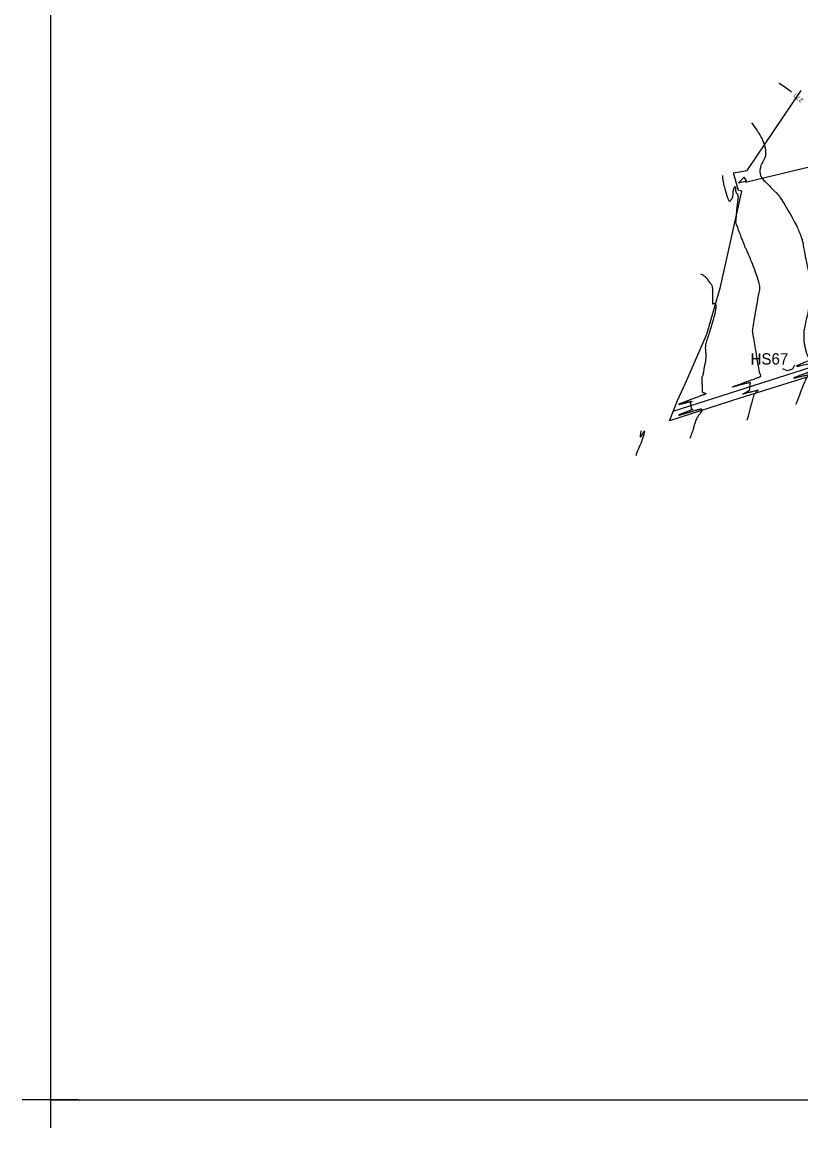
# Model space of a CAD drawing. Extents: x -478645 to -472650, y -1118147 to -1113892.
# Drawn here: x -478645 to -477955, y -1118147 to -1117166 of the extents above; entities that cross this region are included whole.
import ezdxf

# ---------------------------------------------------------------- set-up
doc = ezdxf.new("R2010")
doc.units = 0
for name, color, linetype in [('cestní_příkop_návrh', 7, 'Continuous'), ('cesty', 7, 'Continuous'), ('hospodářské sjezdy', 7, 'Continuous'), ('Implicitní', 7, 'Continuous'), ('ObPÚ', 7, 'Continuous'), ('silnice', 7, 'Continuous'), ('Vrstevnice_hlavni', 7, 'Continuous'), ('Vrstevnice_popis', 7, 'Continuous'), ('Vrstevnice_vedlejsi', 7, 'Continuous'), ('Z_razitko', 7, 'Continuous')]:
    doc.layers.add(name, color=color, linetype=linetype)

msp = doc.modelspace()

# ---------------------------------------------------------------- linework, layer by layer
at = {"layer": 'cestní_příkop_návrh'}
msp.add_lwpolyline([(-478004.329, -1117308.16), (-477706.253, -1117236.161), (-477707.935, -1117239.207)], dxfattribs=at)
at = {"layer": 'cesty'}
msp.add_line((-478003.676, -1117307.068), (-478005.553, -1117303.536), dxfattribs=at)
msp.add_lwpolyline([(-478005.553, -1117303.536), (-478010.749, -1117308.562), (-478003.676, -1117307.068)], dxfattribs=at)
at = {"layer": 'hospodářské sjezdy'}
for p, q in [((-477960.951, -1117470.316), (-477962.923, -1117474.099)), ((-477967.582, -1117475.568), (-477971.367, -1117473.601)), ((-477962.923, -1117474.099), (-477967.582, -1117475.568))]:
    msp.add_line(p, q, dxfattribs=at)
at = {"layer": 'Implicitní'}
for p, q in [((-478620.405, -1118096.842), (-478620.405, -1118146.842)), ((-478620.405, -1118096.842), (-478620.405, -1118146.842)), ((-478620.405, -1118096.842), (-478620.405, -1118146.842)), ((-478620.405, -1118096.842), (-478620.405, -1118146.842)), ((-478595.405, -1118121.842), (-478645.405, -1118121.842)), ((-478595.405, -1118121.842), (-478645.405, -1118121.842)), ((-478595.405, -1118121.842), (-478645.405, -1118121.842)), ((-478595.405, -1118121.842), (-478645.405, -1118121.842))]:
    msp.add_line(p, q, dxfattribs=at)
at = {"layer": 'ObPÚ'}
msp.add_lwpolyline([(-477945.12, -1117479.46), (-478009.37, -1117499.81), (-478071.71, -1117519.91), (-478064.79, -1117501.64), (-478057.71, -1117486.26), (-478038.68, -1117442.8), (-478036.665, -1117435.774), (-478026.64, -1117400.81), (-478007.71, -1117316.06), (-478010.717, -1117315.486), (-478014.94, -1117299.9), (-478003.02, -1117297.83), (-477955.02, -1117226.727)], dxfattribs=at)
at = {"layer": 'silnice'}
msp.add_lwpolyline([(-478068.596, -1117511.329), (-477917.95, -1117462.993), (-477779.219, -1117418.245), (-477732.944, -1117407.585), (-477720.808, -1117405.048), (-477704.588, -1117403.835), (-477689.402, -1117401.926), (-477652.852, -1117401.691), (-477590.784, -1117403.37), (-477332.447, -1117414.279), (-477204.956, -1117416.797), (-477142.049, -1117416.797), (-477096.756, -1117410.083), (-477036.34, -1117397.174), (-476978.492, -1117379.033), (-476883.712, -1117344.626), (-476756.221, -1117298.47), (-476633.763, -1117254.832), (-476588.47, -1117242.245), (-476550.726, -1117234.692)], dxfattribs=at)
at = {"layer": 'Vrstevnice_hlavni'}
msp.add_spline([(-477974.913, -1117220.071), (-477973.154, -1117221.178), (-477963.793, -1117227.865)], degree=3, dxfattribs=at)
at = {"layer": 'Vrstevnice_vedlejsi'}
msp.add_line((-478053.213, -1117534.03), (-478053.687, -1117535.309), dxfattribs=at)
for points in [[(-477998.879, -1117255.557), (-477998.727, -1117255.77), (-477994.613, -1117261.766), (-477989.226, -1117270.883), (-477986.788, -1117279.171), (-477987.299, -1117286.631), (-477990.759, -1117293.261), (-477991.682, -1117299.15), (-477990.068, -1117304.296), (-477985.915, -1117308.701), (-477982.328, -1117312.403), (-477979.306, -1117315.404), (-477976.849, -1117317.702), (-477973.612, -1117321.957), (-477969.594, -1117328.168), (-477964.797, -1117336.336), (-477960.899, -1117343.504), (-477957.9, -1117349.67), (-477955.8, -1117354.835), (-477954.323, -1117359.055), (-477953.469, -1117362.331), (-477953.239, -1117364.661), (-477952.282, -1117369.883), (-477950.598, -1117377.995), (-477948.188, -1117388.997), (-477946.693, -1117397.801), (-477946.113, -1117404.405), (-477946.449, -1117408.81), (-477947.352, -1117414.723), (-477948.823, -1117422.144), (-477950.861, -1117431.072), (-477952.177, -1117437.645), (-477952.771, -1117441.863), (-477952.644, -1117443.726), (-477952.589, -1117445.223), (-477952.606, -1117446.354), (-477952.696, -1117447.119), (-477952.711, -1117448.007), (-477952.649, -1117449.018), (-477952.512, -1117450.153), (-477952.156, -1117452.114), (-477951.583, -1117454.901), (-477950.791, -1117458.515), (-477949.91, -1117461.246), (-477948.939, -1117463.094), (-477947.878, -1117464.059), (-477947.136, -1117464.728), (-477946.712, -1117465.101), (-477946.606, -1117465.179), (-477946.495, -1117465.26), (-477946.379, -1117465.346), (-477946.257, -1117465.436), (-477946.233, -1117465.524), (-477946.307, -1117465.609), (-477946.478, -1117465.691), (-477946.651, -1117465.772), (-477946.824, -1117465.851), (-477946.999, -1117465.928), (-477947.792, -1117466.25), (-477949.203, -1117466.816), (-477951.232, -1117467.627), (-477953.439, -1117468.556), (-477955.824, -1117469.604), (-477958.387, -1117470.771), (-477959.194, -1117471.349), (-477958.243, -1117471.339)], [(-477991.867, -1117477.245), (-477991.928, -1117477.172), (-477992.04, -1117476.677), (-477992.202, -1117475.763), (-477992.413, -1117474.428), (-477993.107, -1117470.277), (-477994.282, -1117463.311), (-477995.94, -1117453.528), (-477997.123, -1117446.591), (-477997.83, -1117442.497), (-477998.062, -1117441.249), (-477997.593, -1117436.785), (-477996.423, -1117429.106), (-477994.553, -1117418.212), (-477993.126, -1117410.136), (-477992.143, -1117404.879), (-477991.604, -1117402.439), (-477992.237, -1117398.118), (-477994.043, -1117391.915), (-477997.021, -1117383.831), (-477999.558, -1117377.283), (-478001.654, -1117372.273), (-478003.307, -1117368.799), (-478004.636, -1117365.887), (-478005.64, -1117363.535), (-478006.319, -1117361.745), (-478007.439, -1117358.786), (-478009, -1117354.657), (-478011.003, -1117349.359), (-478012.316, -1117345.574), (-478012.939, -1117343.304), (-478012.872, -1117342.547), (-478012.777, -1117341.561), (-478012.655, -1117340.344), (-478012.505, -1117338.897), (-478012.348, -1117337.07), (-478012.182, -1117334.863), (-478012.009, -1117332.276), (-478011.775, -1117329.718), (-478011.478, -1117327.189), (-478011.12, -1117324.688), (-478010.876, -1117322.931), (-478010.745, -1117321.917), (-478010.728, -1117321.646), (-478010.753, -1117321.243), (-478010.821, -1117320.708), (-478010.93, -1117320.041), (-478011.029, -1117319.606), (-478011.115, -1117319.402), (-478011.19, -1117319.431), (-478011.241, -1117319.41), (-478011.268, -1117319.341), (-478011.271, -1117319.224), (-478011.447, -1117318.941), (-478011.795, -1117318.493), (-478012.316, -1117317.879), (-478012.672, -1117317.097), (-478012.863, -1117316.147), (-478012.89, -1117315.028), (-478012.892, -1117314.215), (-478012.869, -1117313.71), (-478012.821, -1117313.512), (-478012.909, -1117313.243), (-478013.131, -1117312.902), (-478013.489, -1117312.491), (-478013.809, -1117312.342), (-478014.093, -1117312.455), (-478014.34, -1117312.83), (-478014.581, -1117313.247), (-478014.817, -1117313.705), (-478015.046, -1117314.206), (-478015.238, -1117314.822), (-478015.392, -1117315.554), (-478015.508, -1117316.401), (-478015.602, -1117317.301), (-478015.672, -1117318.253), (-478015.72, -1117319.257), (-478015.808, -1117320.173), (-478015.935, -1117321.003), (-478016.103, -1117321.746), (-478016.33, -1117322.362), (-478016.618, -1117322.853), (-478016.967, -1117323.218), (-478017.343, -1117323.742), (-478017.748, -1117324.426), (-478018.182, -1117325.269), (-478018.755, -1117325.029), (-478019.468, -1117323.706), (-478020.32, -1117321.3), (-478021.282, -1117318.195), (-478022.355, -1117314.389), (-478023.538, -1117309.884), (-478024.297, -1117305.737), (-478024.625, -1117302.334)], [(-478044.323, -1117389.497), (-478042.996, -1117389.964), (-478040.645, -1117391.528), (-478038.938, -1117393.157), (-478037.876, -1117394.852), (-478036.855, -1117396.325), (-478035.874, -1117397.575), (-478034.935, -1117398.602), (-478034.275, -1117399.76), (-478033.895, -1117401.05), (-478033.795, -1117402.47), (-478033.734, -1117403.559), (-478033.712, -1117404.316), (-478033.729, -1117404.741), (-478033.725, -1117405.596), (-478033.699, -1117406.882), (-478033.652, -1117408.598), (-478033.647, -1117410.423), (-478033.685, -1117412.357), (-478033.765, -1117414.398), (-478033.662, -1117415.636), (-478033.377, -1117416.07), (-478032.909, -1117415.7), (-478032.433, -1117415.597), (-478031.948, -1117415.763), (-478031.455, -1117416.196), (-478031.095, -1117416.556), (-478030.869, -1117416.842), (-478030.778, -1117417.054), (-478030.702, -1117417.25), (-478030.642, -1117417.43), (-478030.599, -1117417.594), (-478030.633, -1117418.265), (-478030.746, -1117419.442), (-478030.936, -1117421.127), (-478031.189, -1117422.771), (-478031.506, -1117424.376), (-478031.885, -1117425.94), (-478032.413, -1117427.911), (-478033.089, -1117430.288), (-478033.913, -1117433.072), (-478034.768, -1117435.929), (-478035.655, -1117438.861), (-478036.572, -1117441.865), (-478037.258, -1117444.074), (-478037.711, -1117445.486), (-478037.933, -1117446.102), (-478038.323, -1117447.233), (-478038.882, -1117448.881), (-478039.609, -1117451.044), (-478039.974, -1117453.668), (-478039.978, -1117456.752), (-478039.62, -1117460.297), (-478039.614, -1117463.766), (-478039.96, -1117467.16), (-478040.659, -1117470.478), (-478041.215, -1117473.309), (-478041.627, -1117475.65), (-478041.895, -1117477.504), (-478042.188, -1117478.963), (-478042.508, -1117480.028), (-478042.852, -1117480.698), (-478043.034, -1117482.402), (-478043.052, -1117485.14), (-478042.907, -1117488.911), (-478042.811, -1117491.623), (-478042.763, -1117493.276), (-478042.764, -1117493.87), (-478042.605, -1117494.312), (-478042.286, -1117494.604), (-478041.807, -1117494.745), (-478041.205, -1117494.94), (-478040.478, -1117495.19), (-478039.628, -1117495.494), (-478039.61, -1117495.88), (-478040.424, -1117496.348), (-478042.07, -1117496.896), (-478043.579, -1117497.431), (-478044.951, -1117497.952), (-478046.187, -1117498.458), (-478047.753, -1117499.08), (-478049.649, -1117499.817), (-478051.876, -1117500.669), (-478053.635, -1117501.33), (-478054.925, -1117501.799), (-478055.746, -1117502.077), (-478056.417, -1117502.312), (-478056.936, -1117502.505), (-478057.304, -1117502.655), (-478058.15, -1117502.98), (-478059.473, -1117503.48)], [(-477958.243, -1117471.339), (-477955.536, -1117470.741), (-477952.915, -1117470.142), (-477950.378, -1117469.541), (-477947.927, -1117468.939), (-477946.283, -1117468.538), (-477945.445, -1117468.338), (-477945.414, -1117468.339), (-477945.712, -1117468.473), (-477946.339, -1117468.742), (-477947.296, -1117469.144), (-477947.728, -1117469.923), (-477947.635, -1117471.079), (-477947.017, -1117472.611), (-477946.597, -1117473.709), (-477946.375, -1117474.371), (-477946.35, -1117474.598), (-477946.374, -1117474.773), (-477946.445, -1117474.897), (-477946.564, -1117474.97), (-477946.676, -1117475.037), (-477946.782, -1117475.1), (-477946.881, -1117475.157), (-477946.943, -1117475.205), (-477946.968, -1117475.243), (-477946.957, -1117475.27), (-477947.157, -1117475.466), (-477947.57, -1117475.831), (-477948.194, -1117476.365), (-477948.672, -1117476.747), (-477949.004, -1117476.976), (-477949.191, -1117477.054), (-477949.465, -1117477.156), (-477949.826, -1117477.283), (-477950.274, -1117477.435), (-477951.24, -1117477.772), (-477952.723, -1117478.294), (-477954.724, -1117479.003), (-477956.35, -1117479.597), (-477957.602, -1117480.076), (-477958.479, -1117480.441), (-477959.413, -1117480.834), (-477960.402, -1117481.255), (-477961.448, -1117481.704), (-477961.603, -1117481.871), (-477960.869, -1117481.757), (-477959.244, -1117481.361), (-477957.105, -1117480.843), (-477954.45, -1117480.202), (-477951.281, -1117479.438), (-477949.178, -1117478.982), (-477948.142, -1117478.834), (-477948.174, -1117478.994), (-477948.491, -1117479.411), (-477949.094, -1117480.085), (-477949.982, -1117481.016), (-477951.543, -1117484.163), (-477953.776, -1117489.526), (-477956.682, -1117497.105), (-477959.001, -1117502.97), (-477959.941, -1117505.268)], [(-478003.144, -1117519.112), (-478003.132, -1117519.091), (-478002.849, -1117518.531), (-478002.564, -1117517.866), (-478002.277, -1117517.095), (-478001.519, -1117514.373), (-478000.289, -1117509.7), (-477998.587, -1117503.075), (-477997.307, -1117498.528), (-477996.448, -1117496.058), (-477996.011, -1117495.664), (-477995.494, -1117495.164), (-477994.897, -1117494.557), (-477994.22, -1117493.842), (-477993.709, -1117493.305), (-477993.364, -1117492.946), (-477993.185, -1117492.764), (-477993.124, -1117492.659), (-477993.181, -1117492.63), (-477993.356, -1117492.676), (-477993.771, -1117492.785), (-477994.426, -1117492.954), (-477995.322, -1117493.185), (-477996.795, -1117493.562), (-477998.846, -1117494.085), (-478001.473, -1117494.753), (-478003.611, -1117495.312), (-478005.26, -1117495.76), (-478006.419, -1117496.098), (-478006.996, -1117496.219), (-478006.993, -1117496.123), (-478006.408, -1117495.809), (-478005.709, -1117495.438), (-478004.894, -1117495.01), (-478003.965, -1117494.524), (-478003.169, -1117494.089), (-478002.505, -1117493.706), (-478001.974, -1117493.373), (-478001.536, -1117493.087), (-478001.191, -1117492.847), (-478000.937, -1117492.652), (-478000.751, -1117492.194), (-478000.632, -1117491.473), (-478000.581, -1117490.488), (-478000.498, -1117489.492), (-478000.385, -1117488.485), (-478000.24, -1117487.467), (-478000.128, -1117486.703), (-478000.048, -1117486.194), (-478000.001, -1117485.94), (-477999.965, -1117485.766), (-477999.941, -1117485.673), (-477999.928, -1117485.661), (-478000.489, -1117485.799), (-478001.623, -1117486.089), (-478003.33, -1117486.529), (-478005.282, -1117487.037), (-478007.479, -1117487.611), (-478009.922, -1117488.252), (-478011.864, -1117488.767), (-478013.305, -1117489.157), (-478014.246, -1117489.421), (-478014.977, -1117489.616), (-478015.498, -1117489.744), (-478015.809, -1117489.803), (-478015.836, -1117489.758), (-478015.578, -1117489.608), (-478015.036, -1117489.355), (-478014.549, -1117489.136), (-478014.118, -1117488.952), (-478013.741, -1117488.803), (-478012.405, -1117488.306), (-478010.108, -1117487.462), (-478006.85, -1117486.27), (-478004.315, -1117485.357), (-478002.502, -1117484.722), (-478001.412, -1117484.367), (-477999.922, -1117483.843), (-477998.032, -1117483.15), (-477995.742, -1117482.288), (-477994.054, -1117481.654), (-477992.967, -1117481.248), (-477992.483, -1117481.068), (-477991.998, -1117480.879), (-477991.512, -1117480.68), (-477991.026, -1117480.472), (-477990.843, -1117480.006), (-477990.962, -1117479.282), (-477991.383, -1117478.3), (-477991.685, -1117477.622), (-477991.867, -1117477.245)], [(-478059.473, -1117503.48), (-478061.273, -1117504.155), (-478062.505, -1117504.62), (-478063.169, -1117504.874), (-478063.265, -1117504.919), (-478063.348, -1117504.951), (-478063.419, -1117504.972), (-478063.477, -1117504.981), (-478063.524, -1117504.995), (-478063.56, -1117505.013), (-478063.585, -1117505.036), (-478063.595, -1117505.066), (-478063.591, -1117505.103), (-478063.57, -1117505.147), (-478063.526, -1117505.177), (-478063.458, -1117505.194), (-478063.366, -1117505.198), (-478063.254, -1117505.189), (-478063.124, -1117505.167), (-478062.974, -1117505.132), (-478062.359, -1117504.978), (-478061.278, -1117504.705), (-478059.732, -1117504.311), (-478058.385, -1117503.975), (-478057.239, -1117503.697), (-478056.293, -1117503.477), (-478055.194, -1117503.201), (-478053.942, -1117502.871), (-478052.538, -1117502.485), (-478051.841, -1117502.369), (-478051.851, -1117502.521), (-478052.569, -1117502.943), (-478053.063, -1117503.23), (-478053.334, -1117503.384), (-478053.381, -1117503.404), (-478053.347, -1117503.774), (-478053.23, -1117504.495), (-478053.03, -1117505.565), (-478052.853, -1117506.552), (-478052.698, -1117507.454), (-478052.564, -1117508.272), (-478052.466, -1117508.842), (-478052.403, -1117509.165), (-478052.374, -1117509.239), (-478052.188, -1117509.294), (-478051.845, -1117509.328), (-478051.344, -1117509.342), (-478051.064, -1117509.394), (-478051.005, -1117509.486), (-478051.168, -1117509.616), (-478051.427, -1117509.761), (-478051.782, -1117509.921), (-478052.234, -1117510.097), (-478052.683, -1117510.269), (-478053.128, -1117510.439), (-478053.57, -1117510.606), (-478054.428, -1117510.934), (-478055.701, -1117511.423), (-478057.392, -1117512.072), (-478059.194, -1117512.787), (-478061.11, -1117513.568), (-478063.138, -1117514.415), (-478063.798, -1117514.79), (-478063.089, -1117514.692), (-478061.01, -1117514.123), (-478059.39, -1117513.667), (-478058.228, -1117513.324), (-478057.524, -1117513.095), (-478056.651, -1117512.821), (-478055.61, -1117512.502), (-478054.401, -1117512.139), (-478052.948, -1117511.707), (-478051.253, -1117511.208), (-478049.313, -1117510.64), (-478047.84, -1117510.209), (-478046.831, -1117509.914), (-478046.288, -1117509.755), (-478045.694, -1117509.584), (-478045.048, -1117509.401), (-478044.351, -1117509.205), (-478043.802, -1117509.228), (-478043.401, -1117509.471), (-478043.149, -1117509.932), (-478042.982, -1117510.283), (-478042.902, -1117510.524), (-478042.908, -1117510.653), (-478043.448, -1117511.466), (-478044.521, -1117512.962), (-478046.128, -1117515.142), (-478047.422, -1117517.235), (-478048.402, -1117519.244), (-478049.068, -1117521.166), (-478049.621, -1117522.911), (-478050.059, -1117524.479), (-478050.382, -1117525.869), (-478051.434, -1117529.052), (-478053.213, -1117534.03)], [(-478097.26, -1117528.759), (-478097.327, -1117534.259), (-478094.062, -1117528.696), (-478094.59, -1117531.824), (-478098.909, -1117543.642), (-478101.702, -1117550.697)]]:
    msp.add_spline(points, degree=3, dxfattribs=at)
at = {"layer": 'Z_razitko'}
msp.add_lwpolyline([(-478620.405, -1118121.842), (-472675.405, -1118121.842), (-472675.405, -1113916.842), (-478620.405, -1113916.842)], close=True, dxfattribs=at)

# ---------------------------------------------------------------- texts
at = {"layer": 'hospodářské sjezdy'}
msp.add_text('HS67', height=10, rotation=359.999994, dxfattribs=at).set_placement((-477999.969, -1117469.838))
at = {"layer": 'Vrstevnice_popis'}
msp.add_text(' 270 ', height=4, rotation=137.983368, dxfattribs=at).set_placement((-477951.692, -1117236.071))

doc.saveas('drawing.dxf')
